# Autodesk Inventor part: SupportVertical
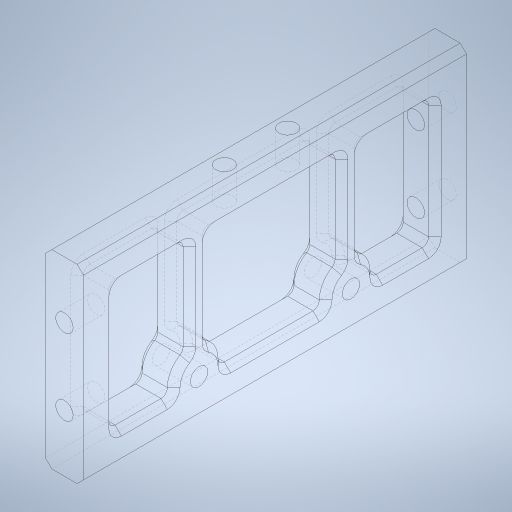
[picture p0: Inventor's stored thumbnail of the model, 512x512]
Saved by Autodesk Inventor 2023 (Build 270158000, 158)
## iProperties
Created: 2023-10
Part Number: SupportVertical
Material: Aluminum 7075
Document SubType Name: Modeling
Designer: tornqvih
Density: 2.81 g/cm^3
Appearance: Satin - Brushed Heavy
Mass: 139.831 g
Surface Area: 196.874 cm^2
Volume: 49.7618 cm^3
Author: tornqvih
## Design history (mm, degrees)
sketch "Sketch1"
  geometry: L1 (-30, 60.5)-(30, 60.5); L2 (30, 60.5)-(30, -60.5); L3 (30, -60.5)-(-30, -60.5); L4 (-30, -60.5)-(-30, 60.5); L5 (-30, 60.5)-(30, -60.5); L6 (30, 60.5)-(-30, -60.5); 1 further point
  constraints: 12 end point, 2 midpoint, 2 parallel, 1 horizontal, 1 perpendicular
  dimensions: "d0" = 121 distance of L1.end L2.end; "d1" = 60 distance of L1.start L1.end
extrude "Extrusion1" new body sketch "Sketch1" distance "d2" = 12; taper "d3" = 0 deg
sketch "Sketch2"
  geometry: L1 (-50.5, 20)-(50.5, 20); L2 (50.5, 20)-(50.5, -20); L3 (50.5, -20)-(-50.5, -20); L4 (-50.5, -20)-(-50.5, 20); L5 (0, -42)-(0, 42) reference; L6 (84.7, 0)-(-84.7, 0) reference; L7 (60.5, 30)-(-60.5, 30) reference; L8 (-60.5, 30)-(-60.5, -30) reference; L9 (-60.5, -30)-(60.5, -30) reference; L10 (60.5, -30)-(60.5, 30) reference; 2 further points
  constraints: 8 end point, 2 parallel, 2 point on line, 2 symmetric about line, 1 horizontal, 1 perpendicular
  dimensions: "d4" = 10 distance between parallel lines of L7 L1; "d5" = 10 distance between parallel lines of L8 L4; "d52" = 10 distance between parallel lines of L9 L3; "d54" = 10 distance between parallel lines of L10 L2
extrude "Extrusion2" cut sketch "Sketch2" extent not by distance; stored distance "d9" = 10; taper "d10" = 0 deg
sketch "Sketch7"
  geometry: L1 (-40, 0)-(30, 0) reference; L2 (-30, 60.5)-(-30, -60.5) reference; L3 (20, -50.5)-(20, 50.5) reference; L4 (20, 27)-(-10.584, 27); L5 (20, 21)-(-10.584, 21); L6 (20, -21)-(-10.584, -21); L7 (20, -27)-(-10.584, -27); C1 r 8 at (-18, -24); A1 r 8 centre (-18, 24) between (-10.584, 27) and (-10.584, 21); 5 further points
  constraints: 8 end point, 5 symmetric about line, 2 centre point, 2 point on circle, 2 point on line, 1 parallel, 1 perpendicular
  dimensions: "d55" = 16 diameter of A1; "d56" = 24 distance from line of L1 A1.centre; "d57" = 12 distance from line of L2 A1.centre; "d58" = 3 distance from line of A1.centre L4; "d59" = 3 distance from line of A1.centre L5; "d60" = 16 diameter of C1
extrude "Extrusion3" join sketch "Sketch7" distance "d61" = 12; taper "d62" = 0 deg
sketch "Sketch3"
  geometry: L1 (0, 60)-(0, 0) reference; L2 (0, 60)-(12, 60) reference; L3 (0, 0)-(12, 0) reference; 3 further points
  constraints: 1 vertical alignment
  dimensions: "d12" = 6 distance from line of L1 point (6, 42); "d13" = 18 distance from line of L2 point (6, 42); "d14" = 18 distance from line of L3 point (6, 18)
hole "Hole1" sketch "Sketch3" at (6, 42), (6, 18) diameter "d15" = 5.5; stored, may be unused: countersink angle "d19" = 90 deg, drill point angle "d21" = 118 deg; dims "d16" = 6, "d17" = 4, "d18" = 2, "d20" = 10
sketch "Sketch4"
  geometry: C1 r 2.75 at (-6, 42) reference; C2 r 2.75 at (-6, 18) reference; 2 further points
  constraints: 2 coincident
hole "Hole2" sketch "Sketch4" at (-6, 42), (-6, 18) diameter "d25" = 5.5; stored, may be unused: countersink angle "d29" = 90 deg, drill point angle "d31" = 118 deg; dims "d26" = 6, "d27" = 4, "d28" = 2, "d30" = 10
sketch "Sketch5"
  geometry: L1 (0, 121)-(0, 0) reference; 5 further points
  constraints: 2 vertical alignment, 1 horizontal alignment, 1 midpoint
  dimensions: "d32" = 6 distance from line of L1 point (6, 60.5); "d33" = 10 distance of point (6, 50.5) point (6, 60.5); "d34" = 10 distance of point (6, 70.5) point (6, 60.5)
hole "Hole3" sketch "Sketch5" at (6, 50.5), (6, 70.5) diameter "d35" = 5.5; stored, may be unused: countersink angle "d39" = 90 deg, drill point angle "d41" = 118 deg; dims "d36" = 6, "d37" = 4, "d38" = 2, "d40" = 10
sketch "Sketch6"
  geometry: L1 (0, -42)-(0, 42) reference; L2 (-60.5, -30)-(60.5, -30) reference; 3 further points
  constraints: 1 symmetric about line
  dimensions: "d44" = 12 distance from line of L2 point (-24, -18); "d63" = 24 distance from line of L1 point (-24, -18)
hole "Hole4" sketch "Sketch6" at (-24, -18), (24, -18) diameter "d45" = 5.5; stored, may be unused: countersink angle "d49" = 90 deg, drill point angle "d51" = 118 deg; dims "d46" = 6, "d47" = 4, "d48" = 2, "d50" = 10
fillet "Fillet1" dims "d64" = 2
chamfer "Chamfer1" distance "d66" = 2; stored, may be unused: second distance "d67" = 2, angle "d68" = 45 deg
body "Solid1"
